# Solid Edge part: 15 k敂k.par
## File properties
Author: Henri
Template: Normal.par
Last saved by: Henri
Revision: 5
Application: Solid Edge
Accuracy: 0,990
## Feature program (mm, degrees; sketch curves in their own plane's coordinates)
sketch for "unnamed Protrusion 1" plane through (0, 0, 0) normal (0, 0, 1) x-axis (1, 0, 0)
  line (25, -25) -> (-100, -25)
  line (-100, -25) -> (-140, -25)
  line (-140, 25) -> (-140, -25)
  line (-100, 25) -> (-140, 25)
  line (-100, 25) -> (100, 25)
  line (100, 25) -> (100, -82.051)
  line (100, -82.051) -> (25, -82.051)
  line (25, -82.051) -> (25, -25)
extrude "unnamed Protrusion 1" add finite 1 along -normal
sketch for "ExtrudedProtrusion_2" plane through (0, -28.5255, 0) normal (0, 0, 1) x-axis (1, 0, 0)
  line (25, 53.5255) -> (25, -53.5255)
  line (25, -53.5255) -> (100, -53.5255)
  line (100, 53.5255) -> (100, -53.5255)
  line (25, 53.5255) -> (100, 53.5255)
extrude "ExtrudedProtrusion_2" add finite 40 along +normal
sketch for "ExtrudedCutout_1" plane through (62.5, -28.5255, 40) normal (0, 0, 1) x-axis (1, 0, 0)
  line (-37.5, -46.0255) -> (22.5, -46.0255)
  line (22.5, -46.0255) -> (30, -38.5255)
  line (30, 38.5255) -> (30, -38.5255)
  line (22.5, 46.0255) -> (30, 38.5255)
  line (-37.5, 46.0255) -> (22.5, 46.0255)
  line (-37.5, 46.0255) -> (-37.5, -46.0255)
extrude "ExtrudedCutout_1" cut finite 20 along -normal
sketch for "ExtrudedCutout_2" plane through (62.5, -28.5255, 40) normal (0, 0, 1) x-axis (1, 0, 0)
  line (10, 26.0255) -> (10, -26.0255)
  line (10, -26.0255) -> (-37.5, -26.0255)
  line (-37.5, 26.0255) -> (-37.5, -26.0255)
  line (-37.5, 26.0255) -> (10, 26.0255)
extrude "ExtrudedCutout_2" cut finite 40 along -normal
sketch for "ExtrudedProtrusion_3" plane through (62.5, -28.5255, 40) normal (0, 0, 1) x-axis (0, 1, 0)
  arc centre (-22.0255, -6) radius 1.5 from (-23.5255, -6) to (-22.0255, -7.5) ccw
  line (22.0255, -7.5) -> (-22.0255, -7.5)
  arc centre (22.0255, -6) radius 1.5 from (22.0255, -7.5) to (23.5255, -6) ccw
  line (23.5255, 33.5) -> (23.5255, -6)
  arc centre (22.0255, 33.5) radius 1.5 from (23.5255, 33.5) to (22.0255, 35) ccw
  line (-22.0255, 35) -> (22.0255, 35)
  arc centre (-22.0255, 33.5) radius 1.5 from (-23.5255, 33.5) to (-22.0255, 35) cw
  line (-23.5255, -6) -> (-23.5255, 33.5)
extrude "ExtrudedProtrusion_3" add finite 2.5 along -normal
lofted protrusion "unnamed LoftedProtrusion 1"
sketch for "unnamed Protrusion 2" plane through (-13.75, -14.7755, 20) normal (0, 0, 1) x-axis (1, 0, 0)
  line (61.5, -14.7755) -> (58, -14.7755)
  arc centre (58, -14.2755) radius 0.5 from (57.5, -14.2755) to (58, -14.7755) ccw
  line (57.5, -14.2755) -> (57.5, -13.2755)
  arc centre (58, -13.2755) radius 0.5 from (57.5, -13.2755) to (58, -12.7755) cw
  line (58, -12.7755) -> (61.5, -12.7755)
  line (61.5, -12.7755) -> (61.5, -9.2755)
  arc centre (62, -9.2755) radius 0.5 from (61.5, -9.2755) to (62, -8.7755) cw
  line (62, -8.7755) -> (63, -8.7755)
  arc centre (63, -9.2755) radius 0.5 from (63.5, -9.2755) to (63, -8.7755) ccw
  line (63.5, -9.2755) -> (63.5, -12.7755)
  line (63.5, -12.7755) -> (67, -12.7755)
  arc centre (67, -13.2755) radius 0.5 from (67, -12.7755) to (67.5, -13.2755) cw
  line (67.5, -13.2755) -> (67.5, -14.2755)
  arc centre (67, -14.2755) radius 0.5 from (67.5, -14.2755) to (67, -14.7755) cw
  line (67, -14.7755) -> (63.5, -14.7755)
  line (63.5, -14.7755) -> (63.5, -18.2755)
  arc centre (63, -18.2755) radius 0.5 from (63, -18.7755) to (63.5, -18.2755) ccw
  line (63, -18.7755) -> (62, -18.7755)
  arc centre (62, -18.2755) radius 0.5 from (61.5, -18.2755) to (62, -18.7755) ccw
  line (61.5, -18.2755) -> (61.5, -14.7755)
extrude "unnamed Protrusion 2" add through along +normal
fillet "Round_1" radius 1
fillet "Round_3" radius 2.5
sketch for "ExtrudedProtrusion_5" plane through (-13.75, -16.0255, 0) normal (0, 0, 1) x-axis (1, 0, 0)
  line (12.25, -7.4745) -> (12.25, 39.5255)
  line (12.25, 39.5255) -> (-34.75, 39.5255)
  line (-34.75, 39.5255) -> (-34.75, -7.4745)
  line (-34.75, -7.4745) -> (12.25, -7.4745)
extrude "ExtrudedProtrusion_5" add finite 50 along +normal
sketch for "ExtrudedCutout_3" plane through (-25, -23.5, 25) normal (0, -1, 0) x-axis (1, 0, 0)
  line (-18.5, 15) -> (18.5, 15)
  line (18.5, 15) -> (18.5, -10)
  line (18.5, -10) -> (-18.5, -10)
  line (-18.5, -10) -> (-18.5, 15)
extrude "ExtrudedCutout_3" cut finite 45 along -normal
sketch for "ExtrudedProtrusion_7" plane through (-25, -23.5, 25) normal (0, -1, 0) x-axis (1, 0, 0)
  line (-21, -11) -> (-21, 16)
  arc centre (-19.5, 16) radius 1.5 from (-21, 16) to (-19.5, 17.5) cw
  line (-19.5, 17.5) -> (19.5, 17.5)
  arc centre (19.5, 16) radius 1.5 from (19.5, 17.5) to (21, 16) cw
  line (21, 16) -> (21, -11)
  arc centre (19.5, -11) radius 1.5 from (19.5, -12.5) to (21, -11) ccw
  line (19.5, -12.5) -> (-19.5, -12.5)
  arc centre (-19.5, -11) radius 1.5 from (-19.5, -12.5) to (-21, -11) cw
extrude "ExtrudedProtrusion_7" add finite 1.5 along +normal
fillet "Round_4" radius 0.5
swept protrusion "unnamed SweptProtrusion 1"
fillet "Round_6" radius 1.5
sketch for "ExtrudedCutout_4" plane through (-25, 0, 50) normal (0, 0, 1) x-axis (0, 1, 0)
  line (20, 20) -> (-20, 20)
  line (-20, 20) -> (-20, -20)
  line (-20, -20) -> (20, -20)
  line (20, -20) -> (20, 20)
extrude "ExtrudedCutout_4" cut finite 2 along -normal
fillet "Round_7" radius 1.5
sketch for "ExtrudedProtrusion_8" #1 plane through (-25, 0, 48) normal (0, 0, 1) x-axis (0, 1, 0)
  circle centre (7.5, 10) radius 6.25
sketch for "ExtrudedProtrusion_8" #2 plane through (-25, 0, 48) normal (0, 0, 1) x-axis (0, 1, 0)
  circle centre (-12.5, 10) radius 5
sketch for "ExtrudedProtrusion_8" #3 plane through (-25, 0, 48) normal (0, 0, 1) x-axis (0, 1, 0)
  circle centre (-12.5, -10) radius 3.75
sketch for "ExtrudedProtrusion_8" #4 plane through (-25, 0, 48) normal (0, 0, 1) x-axis (0, 1, 0)
  circle centre (7.5, -10) radius 6.25
extrude "ExtrudedProtrusion_8" add finite 1.5 along +normal
fillet "Round_9" radius 0.75
fillet "Round_10" radius 0.25
sketch for "ExtrudedProtrusion_9" plane through (-25, -23.5, 24.25) normal (0, -1, 0) x-axis (1, 0, 0)
  circle centre (-20, 21.25) radius 1.25
extrude "ExtrudedProtrusion_9" add finite 0.5 along +normal
sketch for "ExtrudedProtrusion_10" plane through (-45, -24, 45.5) normal (0, -1, 0) x-axis (1, 0, 0)
  line (-0.125, -1) -> (-0.125, 1)
  line (-0.125, 1) -> (0.125, 1)
  line (0.125, 1) -> (0.125, -1)
  line (0.125, -1) -> (-0.125, -1)
extrude "ExtrudedProtrusion_10" add finite 1.25 along +normal
sketch for "unnamed Cutout 1" #1 plane through (-44.875, -24.625, 45.5) normal (1, 0, 0) x-axis (0, 1, 0)
  line (-0.625, 0.1054) -> (-0.625, 1)
  line (-0.625, 1) -> (0.625, 1)
  arc centre (1.1114, -1.0003) radius 2.0586 from (0.625, 1) to (-0.625, 0.1054) ccw
sketch for "unnamed Cutout 1" #2 plane through (-44.875, -24.625, 45.5) normal (1, 0, 0) x-axis (0, 1, 0)
  arc centre (1.1114, 1.0003) radius 2.0586 from (0.625, -1) to (-0.625, -0.1054) cw
  line (-0.625, -0.1054) -> (-0.625, -1)
  line (-0.625, -1) -> (0.625, -1)
extrude "unnamed Cutout 1" cut through along -normal
fillet "Round_11" radius 0.1
fillet "Round_12" radius 0.05
pattern "PatternOccurrence_1" of "ExtrudedProtrusion_9", "ExtrudedProtrusion_10", "Round_11", "unnamed Cutout 1", "Round_12" along a curve  XDirCount = 6; XDirSpacing = 5 mm
pattern "unnamed Pattern 1"
lofted protrusion "unnamed LoftedProtrusion 2"
fillet "Round_14" radius 0.1
lofted cutout "unnamed LoftedCutout 1"
sketch for "ExtrudedProtrusion_12" plane through (-25, 0, 108) normal (0, 0, 1) x-axis (0, 1, 0)
  line (8.5, -4.5) -> (20.5, -4.5)
  arc centre (20.5, -3) radius 1.5 from (20.5, -4.5) to (22, -3) ccw
  line (22, 3) -> (22, -3)
  arc centre (20.5, 3) radius 1.5 from (20.5, 4.5) to (22, 3) cw
  line (8.5, 4.5) -> (20.5, 4.5)
  arc centre (8.5, 3) radius 1.5 from (7, 3) to (8.5, 4.5) cw
  line (7, -3) -> (7, 3)
  arc centre (8.5, -3) radius 1.5 from (7, -3) to (8.5, -4.5) ccw
extrude "ExtrudedProtrusion_12" add finite 15 along +normal
sketch for "ExtrudedCutout_7" plane through (-25, 0, 108) normal (0, 0, 1) x-axis (0, 1, 0)
  line (20, -3) -> (9, -3)
  arc centre (9, -2.5) radius 0.5 from (8.5, -2.5) to (9, -3) ccw
  line (8.5, -2.5) -> (8.5, 2.5)
  arc centre (9, 2.5) radius 0.5 from (8.5, 2.5) to (9, 3) cw
  line (9, 3) -> (20, 3)
  arc centre (20, 2.5) radius 0.5 from (20, 3) to (20.5, 2.5) cw
  line (20.5, 2.5) -> (20.5, -2.5)
  arc centre (20, -2.5) radius 0.5 from (20, -3) to (20.5, -2.5) ccw
extrude "ExtrudedCutout_7" cut finite 14 along +normal
sketch for "unnamed Protrusion 3" plane through (-155, 0, 0) normal (1, 0, 0) x-axis (0, 1, 0)
  line (7, 113) -> (7, 123)
  line (7, 123) -> (22, 123)
  line (22, 113) -> (22, 123)
  line (7, 113) -> (22, 113)
extrude "unnamed Protrusion 3" add to key point along +normal
sketch for "unnamed Cutout 2" plane through (-155, 0, 0) normal (1, 0, 0) x-axis (0, 1, 0)
  line (21.5, 122.5) -> (21.5, 113.5)
  line (21.5, 113.5) -> (7.5, 113.5)
  line (7.5, 113.5) -> (7.5, 122.5)
  line (7.5, 122.5) -> (21.5, 122.5)
extrude "unnamed Cutout 2" cut finite 132 along +normal
sketch for "unnamed Protrusion 4" plane through (-25, 0, 93) normal (0, 0, 1) x-axis (0, 1, 0)
  line (21.5, -21) -> (23.5, -21)
  line (23.5, -21) -> (23.5, 21)
  line (21.5, 21) -> (23.5, 21)
  line (21.5, 21) -> (21.5, -21)
extrude "unnamed Protrusion 4" add through along -normal
sketch for "ExtrudedProtrusion_16" plane through (-33.75, -16.0255, 0) normal (0, 0, 1) x-axis (0, 1, 0)
  line (-6.4745, 103.75) -> (38.5255, 103.75)
  line (38.5255, 103.75) -> (38.5255, 53.75)
  line (38.5255, 53.75) -> (-6.4745, 53.75)
  line (-6.4745, 53.75) -> (-6.4745, 103.75)
extrude "ExtrudedProtrusion_16" add finite 105 along +normal
sketch for "ExtrudedCutout_9" #1 plane through (-112.5, -22.5, 52.5) normal (0, -1, 0) x-axis (1, 0, 0)
  line (-20, 47.5) -> (-20, -2.5)
  line (-20, -2.5) -> (20, -2.5)
  line (20, 47.5) -> (20, -2.5)
  line (-20, 47.5) -> (20, 47.5)
sketch for "ExtrudedCutout_9" #2 plane through (-112.5, -22.5, 52.5) normal (0, -1, 0) x-axis (1, 0, 0)
  line (-20, -7.5) -> (-20, -47.5)
  line (20, -47.5) -> (-20, -47.5)
  line (20, -7.5) -> (20, -47.5)
  line (-20, -7.5) -> (20, -7.5)
extrude "ExtrudedCutout_9" cut finite 40 along -normal
sketch for "unnamed Protrusion 5" #1 plane through (-112.5, -22.5, 52.5) normal (0, -1, 0) x-axis (1, 0, 0)
  line (22, 49.5) -> (-22, 49.5)
  line (-22, 49.5) -> (-22, -4.5)
  line (-22, -4.5) -> (22, -4.5)
  line (22, -4.5) -> (22, 49.5)
sketch for "unnamed Protrusion 5" #2 plane through (-112.5, -22.5, 52.5) normal (0, -1, 0) x-axis (1, 0, 0)
  line (21, 48.5) -> (-21, 48.5)
  line (-21, 48.5) -> (-21, -3.5)
  line (-21, -3.5) -> (21, -3.5)
  line (21, -3.5) -> (21, 48.5)
sketch for "unnamed Protrusion 5" #3 plane through (-112.5, -22.5, 52.5) normal (0, -1, 0) x-axis (1, 0, 0)
  line (-22, -5.5) -> (-22, -49.5)
  line (-22, -49.5) -> (22, -49.5)
  line (22, -49.5) -> (22, -5.5)
  line (22, -5.5) -> (-22, -5.5)
sketch for "unnamed Protrusion 5" #4 plane through (-112.5, -22.5, 52.5) normal (0, -1, 0) x-axis (1, 0, 0)
  line (-21, -6.5) -> (-21, -48.5)
  line (-21, -48.5) -> (21, -48.5)
  line (21, -48.5) -> (21, -6.5)
  line (21, -6.5) -> (-21, -6.5)
extrude "unnamed Protrusion 5" add finite 1 along +normal
sketch for "unnamed Protrusion 6" #1 plane through (-132.5, -2.5, 75) normal (1, 0, 0) x-axis (0, 1, 0)
  line (-17.5, 9) -> (17.5, 9)
  line (17.5, 10) -> (17.5, 9)
  line (-17.5, 10) -> (17.5, 10)
  line (-17.5, 10) -> (-17.5, 9)
sketch for "unnamed Protrusion 6" #2 plane through (-132.5, -2.5, 75) normal (1, 0, 0) x-axis (0, 1, 0)
  line (-17.5, -6) -> (17.5, -6)
  line (17.5, -6) -> (17.5, -7)
  line (-17.5, -7) -> (17.5, -7)
  line (-17.5, -6) -> (-17.5, -7)
sketch for "unnamed Protrusion 6" #3 plane through (-132.5, -2.5, 75) normal (1, 0, 0) x-axis (0, 1, 0)
  line (-17.5, -44) -> (17.5, -44)
  line (17.5, -43) -> (17.5, -44)
  line (-17.5, -43) -> (17.5, -43)
  line (-17.5, -43) -> (-17.5, -44)
sketch for "unnamed Protrusion 6" #4 plane through (-132.5, -2.5, 75) normal (1, 0, 0) x-axis (0, 1, 0)
  line (-17.5, -59) -> (17.5, -59)
  line (17.5, -59) -> (17.5, -60)
  line (-17.5, -60) -> (17.5, -60)
  line (-17.5, -59) -> (-17.5, -60)
extrude "unnamed Protrusion 6" add through along +normal
sketch for "ExtrudedProtrusion_19" #1 plane through (-112.5, -23.5, 75) normal (0, -1, 0) x-axis (1, 0, 0)
  line (22.25, 27.25) -> (-22.25, 27.25)
  line (-22.25, 27.25) -> (-22.25, -27.25)
  line (-22.25, -27.25) -> (22.25, -27.25)
  line (22.25, -27.25) -> (22.25, 27.25)
sketch for "ExtrudedProtrusion_19" #2 plane through (-112.5, -23.5, 75) normal (0, -1, 0) x-axis (1, 0, 0)
  line (-22.25, -27.75) -> (-22.25, -72.25)
  line (-22.25, -72.25) -> (22.25, -72.25)
  line (22.25, -72.25) -> (22.25, -27.75)
  line (22.25, -27.75) -> (-22.25, -27.75)
extrude "ExtrudedProtrusion_19" add finite 2.5 along +normal
sketch for "ExtrudedProtrusion_20" #1 plane through (-112.5, -26, 75) normal (0, -1, 0) x-axis (1, 0, 0)
  line (17.25, -21.25) -> (17.25, 21.25)
  arc centre (18.25, 21.25) radius 1 from (17.25, 21.25) to (18.25, 22.25) cw
  line (18.25, 22.25) -> (18.75, 22.25)
  arc centre (18.75, 21.25) radius 1 from (18.75, 22.25) to (19.75, 21.25) cw
  line (19.75, -21.25) -> (19.75, 21.25)
  arc centre (18.75, -21.25) radius 1 from (18.75, -22.25) to (19.75, -21.25) ccw
  line (18.25, -22.25) -> (18.75, -22.25)
  arc centre (18.25, -21.25) radius 1 from (18.25, -22.25) to (17.25, -21.25) cw
sketch for "ExtrudedProtrusion_20" #2 plane through (-112.5, -26, 75) normal (0, -1, 0) x-axis (1, 0, 0)
  line (17.25, -33.75) -> (17.25, -66.25)
  arc centre (18.25, -66.25) radius 1 from (17.25, -66.25) to (18.25, -67.25) ccw
  line (18.25, -67.25) -> (19, -67.25)
  arc centre (19, -66.25) radius 1 from (19, -67.25) to (20, -66.25) ccw
  line (20, -33.75) -> (20, -66.25)
  arc centre (19, -33.75) radius 1 from (19, -32.75) to (20, -33.75) cw
  line (18.25, -32.75) -> (19, -32.75)
  arc centre (18.25, -33.75) radius 1 from (17.25, -33.75) to (18.25, -32.75) cw
extrude "ExtrudedProtrusion_20" add finite 3 along +normal
sketch for "unnamed Cutout 3" #1 plane through (-95.25, -27.5, 75) normal (-1, 0, 0) x-axis (0, 0, -1)
  line (-18.75, 1) -> (18.75, 1)
  line (18.75, 1) -> (18.75, -1)
  line (-18.75, -1) -> (18.75, -1)
  line (-18.75, 1) -> (-18.75, -1)
sketch for "unnamed Cutout 3" #2 plane through (-95.25, -27.5, 75) normal (-1, 0, 0) x-axis (0, 0, -1)
  line (36.25, 1) -> (63.75, 1)
  line (63.75, 1) -> (63.75, -1)
  line (36.25, -1) -> (63.75, -1)
  line (36.25, 1) -> (36.25, -1)
extrude "unnamed Cutout 3" cut through along -normal
fillet "Round_16" radius 0.2
fillet "Round_17" radius 1
sketch for "ExtrudedProtrusion_21" plane through (-33.75, -16.0255, 0) normal (0, 0, 1) x-axis (0, 1, 0)
  line (40.5255, 51.25) -> (-6.9745, 51.25)
  line (-6.9745, 51.25) -> (-6.9745, 17.25)
  line (40.5255, 17.25) -> (-6.9745, 17.25)
  line (40.5255, 51.25) -> (40.5255, 17.25)
extrude "ExtrudedProtrusion_21" add finite 50 along +normal
sketch for "ExtrudedCutout_11" #1 plane through (-68, -23, 25) normal (0, -1, 0) x-axis (1, 0, 0)
  line (-14.5, 0.5) -> (-0.5, 0.5)
  line (-0.5, 23.5) -> (-0.5, 0.5)
  line (-0.5, 23.5) -> (-14.5, 23.5)
  arc centre (-14.5, 22.5) radius 1 from (-15.5, 22.5) to (-14.5, 23.5) cw
  line (-15.5, 22.5) -> (-15.5, 1.5)
  arc centre (-14.5, 1.5) radius 1 from (-14.5, 0.5) to (-15.5, 1.5) cw
sketch for "ExtrudedCutout_11" #2 plane through (-68, -23, 25) normal (0, -1, 0) x-axis (1, 0, 0)
  line (-0.5, -0.5) -> (-0.5, -23.5)
  line (-0.5, -23.5) -> (-14.5, -23.5)
  arc centre (-14.5, -22.5) radius 1 from (-14.5, -23.5) to (-15.5, -22.5) cw
  line (-15.5, -1.5) -> (-15.5, -22.5)
  arc centre (-14.5, -1.5) radius 1 from (-15.5, -1.5) to (-14.5, -0.5) cw
  line (-14.5, -0.5) -> (-0.5, -0.5)
sketch for "ExtrudedCutout_11" #3 plane through (-68, -23, 25) normal (0, -1, 0) x-axis (1, 0, 0)
  arc centre (14.5, 1.5) radius 1 from (14.5, 0.5) to (15.5, 1.5) ccw
  line (15.5, 22.5) -> (15.5, 1.5)
  arc centre (14.5, 22.5) radius 1 from (14.5, 23.5) to (15.5, 22.5) cw
  line (14.5, 23.5) -> (0.5, 23.5)
  line (0.5, 23.5) -> (0.5, 0.5)
  line (0.5, 0.5) -> (14.5, 0.5)
sketch for "ExtrudedCutout_11" #4 plane through (-68, -23, 25) normal (0, -1, 0) x-axis (1, 0, 0)
  line (14.5, -23.5) -> (0.5, -23.5)
  line (0.5, -0.5) -> (0.5, -23.5)
  line (0.5, -0.5) -> (14.5, -0.5)
  arc centre (14.5, -1.5) radius 1 from (14.5, -0.5) to (15.5, -1.5) cw
  line (15.5, -1.5) -> (15.5, -22.5)
  arc centre (14.5, -22.5) radius 1 from (14.5, -23.5) to (15.5, -22.5) ccw
extrude "ExtrudedCutout_11" cut finite 45 along -normal
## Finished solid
Body 1: solid body, 559 faces, 1263 edges, 736 vertices, 3 internal voids.
  Faces by surface: plane 234, cylinder 175, torus 64, blend 52, sphere 17, spline 17
  Edges by curve: line 712, circle 406, intersection 130, curve on surface 8, ellipse 7
Bounding box of the edges (mm; curved faces can reach further): 255.000 x 107.051 x 124.000, from (-155, -82.051, -1) to (100, 25, 123).
Cylindrical faces by radius (mm): R0.05 x36, R0.1 x4, R0.2 x12, R0.5 x16, R1 x32, R1.25 x6, R1.5 x25, R2.0586 x12, R2.5 x28, R3.75 x1, R5 x1, R6.25 x2
Toroidal faces (ring radius, tube radius in mm): R0.5 r1 x8, R0.8 r0.2 x8, R1 r0.5 x4, R1.15 r0.1 x6, R1.9586 r0.1 x24, R3.5 r0.25 x1, R4.5 r0.75 x1, R4.75 r0.25 x1, R5 r2.5 x6, R5.75 r0.75 x1, R6 r0.25 x2, R7 r0.75 x2
Spherical faces by radius (mm): R1 x4, R1.5 x4, R2.5 x9
Planar faces by outward normal: +x 34, +y 25, +z 37, -x 40, -y 48, -z 28, oblique 22
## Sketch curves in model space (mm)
arc centre (-82.5, -23, 26.5) radius 1 from (-82.5, -23, 25.5) through (-83.2274, -23, 25.8138) to (-83.5, -23, 26.5)
line (-82.5, -23, 25.5) -> (-68.5, -23, 25.5)
line (-68.5, -23, 48.5) -> (-68.5, -23, 25.5)
line (-68.5, -23, 48.5) -> (-82.5, -23, 48.5)
arc centre (-82.5, -23, 47.5) radius 1 from (-83.5, -23, 47.5) through (-83.1862, -23, 48.2274) to (-82.5, -23, 48.5)
line (-83.5, -23, 47.5) -> (-83.5, -23, 26.5)
arc centre (-53.5, -23, 26.5) radius 1 from (-53.5, -23, 25.5) through (-52.7726, -23, 25.8138) to (-52.5, -23, 26.5)
line (-67.5, -23, 25.5) -> (-53.5, -23, 25.5)
line (-67.5, -23, 48.5) -> (-67.5, -23, 25.5)
line (-53.5, -23, 48.5) -> (-67.5, -23, 48.5)
arc centre (-53.5, -23, 47.5) radius 1 from (-53.5, -23, 48.5) through (-52.7726, -23, 48.1862) to (-52.5, -23, 47.5)
line (-52.5, -23, 47.5) -> (-52.5, -23, 26.5)
arc centre (-82.5, -23, 2.5) radius 1 from (-82.5, -23, 1.5) through (-83.2274, -23, 1.8138) to (-83.5, -23, 2.5)
line (-83.5, -23, 23.5) -> (-83.5, -23, 2.5)
arc centre (-82.5, -23, 23.5) radius 1 from (-83.5, -23, 23.5) through (-83.1862, -23, 24.2274) to (-82.5, -23, 24.5)
line (-82.5, -23, 24.5) -> (-68.5, -23, 24.5)
line (-68.5, -23, 24.5) -> (-68.5, -23, 1.5)
line (-68.5, -23, 1.5) -> (-82.5, -23, 1.5)
arc centre (-53.5, -23, 2.5) radius 1 from (-53.5, -23, 1.5) through (-52.7726, -23, 1.8138) to (-52.5, -23, 2.5)
line (-53.5, -23, 1.5) -> (-67.5, -23, 1.5)
line (-67.5, -23, 24.5) -> (-67.5, -23, 1.5)
line (-67.5, -23, 24.5) -> (-53.5, -23, 24.5)
arc centre (-53.5, -23, 23.5) radius 1 from (-53.5, -23, 24.5) through (-52.7726, -23, 24.1862) to (-52.5, -23, 23.5)
line (-52.5, -23, 23.5) -> (-52.5, -23, 2.5)
line (-85, -23, 0) -> (-51, -23, 0)
line (-51, 24.5, 0) -> (-51, -23, 0)
line (-85, 24.5, 0) -> (-51, 24.5, 0)
line (-85, 24.5, 0) -> (-85, -23, 0)
line (-95.25, -26.5, 93.75) -> (-95.25, -26.5, 56.25)
line (-95.25, -28.5, 56.25) -> (-95.25, -26.5, 56.25)
line (-95.25, -28.5, 93.75) -> (-95.25, -28.5, 56.25)
line (-95.25, -28.5, 93.75) -> (-95.25, -26.5, 93.75)
line (-95.25, -26.5, 38.75) -> (-95.25, -26.5, 11.25)
line (-95.25, -28.5, 11.25) -> (-95.25, -26.5, 11.25)
line (-95.25, -28.5, 38.75) -> (-95.25, -28.5, 11.25)
line (-95.25, -28.5, 38.75) -> (-95.25, -26.5, 38.75)
arc centre (-93.75, -26, 96.25) radius 1 from (-93.75, -26, 97.25) through (-93.0226, -26, 96.9362) to (-92.75, -26, 96.25)
line (-94.25, -26, 97.25) -> (-93.75, -26, 97.25)
arc centre (-94.25, -26, 96.25) radius 1 from (-95.25, -26, 96.25) through (-94.9362, -26, 96.9774) to (-94.25, -26, 97.25)
line (-95.25, -26, 53.75) -> (-95.25, -26, 96.25)
arc centre (-94.25, -26, 53.75) radius 1 from (-94.25, -26, 52.75) through (-94.9774, -26, 53.0638) to (-95.25, -26, 53.75)
line (-94.25, -26, 52.75) -> (-93.75, -26, 52.75)
arc centre (-93.75, -26, 53.75) radius 1 from (-93.75, -26, 52.75) through (-93.0226, -26, 53.0638) to (-92.75, -26, 53.75)
line (-92.75, -26, 53.75) -> (-92.75, -26, 96.25)
arc centre (-93.5, -26, 41.25) radius 1 from (-93.5, -26, 42.25) through (-92.7726, -26, 41.9362) to (-92.5, -26, 41.25)
line (-92.5, -26, 41.25) -> (-92.5, -26, 8.75)
arc centre (-93.5, -26, 8.75) radius 1 from (-93.5, -26, 7.75) through (-92.7726, -26, 8.0638) to (-92.5, -26, 8.75)
line (-94.25, -26, 7.75) -> (-93.5, -26, 7.75)
arc centre (-94.25, -26, 8.75) radius 1 from (-95.25, -26, 8.75) through (-94.9362, -26, 8.0226) to (-94.25, -26, 7.75)
line (-95.25, -26, 41.25) -> (-95.25, -26, 8.75)
arc centre (-94.25, -26, 41.25) radius 1 from (-95.25, -26, 41.25) through (-94.9362, -26, 41.9774) to (-94.25, -26, 42.25)
line (-94.25, -26, 42.25) -> (-93.5, -26, 42.25)
line (-134.75, -23.5, 47.75) -> (-90.25, -23.5, 47.75)
line (-90.25, -23.5, 47.75) -> (-90.25, -23.5, 102.25)
line (-90.25, -23.5, 102.25) -> (-134.75, -23.5, 102.25)
line (-134.75, -23.5, 102.25) -> (-134.75, -23.5, 47.75)
line (-134.75, -23.5, 2.75) -> (-90.25, -23.5, 2.75)
line (-90.25, -23.5, 2.75) -> (-90.25, -23.5, 47.25)
line (-90.25, -23.5, 47.25) -> (-134.75, -23.5, 47.25)
line (-134.75, -23.5, 47.25) -> (-134.75, -23.5, 2.75)
line (-132.5, 15, 85) -> (-132.5, 15, 84)
line (-132.5, -20, 84) -> (-132.5, 15, 84)
line (-132.5, -20, 85) -> (-132.5, -20, 84)
line (-132.5, -20, 85) -> (-132.5, 15, 85)
line (-132.5, -20, 15) -> (-132.5, 15, 15)
line (-132.5, -20, 16) -> (-132.5, -20, 15)
line (-132.5, -20, 16) -> (-132.5, 15, 16)
line (-132.5, 15, 16) -> (-132.5, 15, 15)
line (-132.5, 15, 69) -> (-132.5, 15, 68)
line (-132.5, -20, 68) -> (-132.5, 15, 68)
line (-132.5, -20, 69) -> (-132.5, -20, 68)
line (-132.5, -20, 69) -> (-132.5, 15, 69)
line (-132.5, 15, 32) -> (-132.5, 15, 31)
line (-132.5, -20, 31) -> (-132.5, 15, 31)
line (-132.5, -20, 32) -> (-132.5, -20, 31)
line (-132.5, -20, 32) -> (-132.5, 15, 32)
line (-133.5, -22.5, 101) -> (-133.5, -22.5, 49)
line (-133.5, -22.5, 49) -> (-91.5, -22.5, 49)
line (-91.5, -22.5, 49) -> (-91.5, -22.5, 101)
line (-91.5, -22.5, 101) -> (-133.5, -22.5, 101)
line (-133.5, -22.5, 4) -> (-91.5, -22.5, 4)
line (-91.5, -22.5, 4) -> (-91.5, -22.5, 46)
line (-91.5, -22.5, 46) -> (-133.5, -22.5, 46)
line (-133.5, -22.5, 46) -> (-133.5, -22.5, 4)
line (-134.5, -22.5, 3) -> (-90.5, -22.5, 3)
line (-90.5, -22.5, 3) -> (-90.5, -22.5, 47)
line (-90.5, -22.5, 47) -> (-134.5, -22.5, 47)
line (-134.5, -22.5, 47) -> (-134.5, -22.5, 3)
line (-134.5, -22.5, 48) -> (-90.5, -22.5, 48)
line (-90.5, -22.5, 48) -> (-90.5, -22.5, 102)
line (-90.5, -22.5, 102) -> (-134.5, -22.5, 102)
line (-134.5, -22.5, 102) -> (-134.5, -22.5, 48)
line (-132.5, -22.5, 50) -> (-92.5, -22.5, 50)
line (-92.5, -22.5, 100) -> (-92.5, -22.5, 50)
line (-132.5, -22.5, 100) -> (-92.5, -22.5, 100)
line (-132.5, -22.5, 100) -> (-132.5, -22.5, 50)
line (-132.5, -22.5, 45) -> (-132.5, -22.5, 5)
line (-132.5, -22.5, 45) -> (-92.5, -22.5, 45)
line (-92.5, -22.5, 45) -> (-92.5, -22.5, 5)
line (-92.5, -22.5, 5) -> (-132.5, -22.5, 5)
line (-87.5, -22.5, 0) -> (-137.5, -22.5, 0)
line (-137.5, -22.5, 0) -> (-137.5, 22.5, 0)
line (-137.5, 22.5, 0) -> (-87.5, 22.5, 0)
line (-87.5, 22.5, 0) -> (-87.5, -22.5, 0)
line (-155, 22, 113) -> (-155, 22, 123)
line (-155, 7, 113) -> (-155, 22, 113)
line (-155, 7, 113) -> (-155, 7, 123)
line (-155, 7, 123) -> (-155, 22, 123)
line (-155, 7.5, 122.5) -> (-155, 21.5, 122.5)
line (-155, 21.5, 122.5) -> (-155, 21.5, 113.5)
line (-155, 21.5, 113.5) -> (-155, 7.5, 113.5)
line (-155, 7.5, 113.5) -> (-155, 7.5, 122.5)
arc centre (-22, 20.5, 108) radius 1.5 from (-20.5, 20.5, 108) through (-20.9706, 21.5911, 108) to (-22, 22, 108)
line (-20.5, 8.5, 108) -> (-20.5, 20.5, 108)
arc centre (-22, 8.5, 108) radius 1.5 from (-22, 7, 108) through (-20.9089, 7.4706, 108) to (-20.5, 8.5, 108)
line (-22, 7, 108) -> (-28, 7, 108)
arc centre (-28, 8.5, 108) radius 1.5 from (-28, 7, 108) through (-29.0911, 7.4706, 108) to (-29.5, 8.5, 108)
line (-29.5, 8.5, 108) -> (-29.5, 20.5, 108)
arc centre (-28, 20.5, 108) radius 1.5 from (-29.5, 20.5, 108) through (-29.0294, 21.5911, 108) to (-28, 22, 108)
line (-28, 22, 108) -> (-22, 22, 108)
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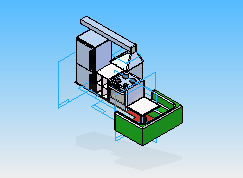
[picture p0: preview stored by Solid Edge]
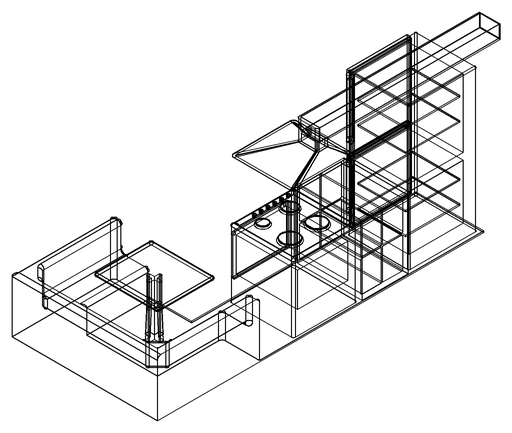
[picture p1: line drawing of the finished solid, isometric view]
